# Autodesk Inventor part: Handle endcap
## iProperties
Created: 2008-10
Part Number: Handle endcap
Document SubType Name: Modeling
Designer: the-dude
Density: 1 g/cm^3
Author: the-dude
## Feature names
1. Revolution1
2. Revolution2
